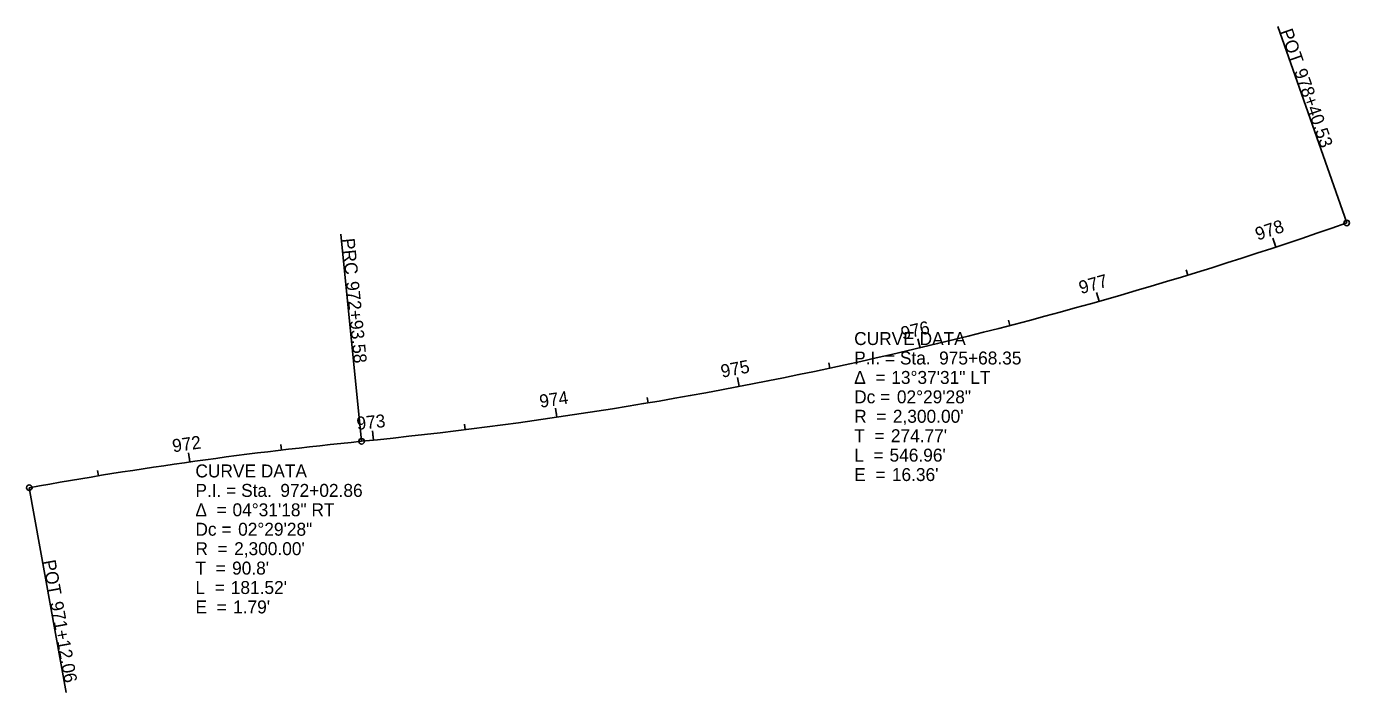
# Model space of a CAD drawing. Extents: x 2192763 to 2198189, y 660254 to 661868.
# Drawn here: x 2192763 to 2193478, y 660254 to 660614 of the extents above; entities that cross this region are included whole.
import ezdxf

# ---------------------------------------------------------------- set-up
doc = ezdxf.new("R2010")
doc.units = 0
for name, color, linetype in [('PM_X_Cells', 7, 'Continuous'), ('PM_X_CL_Double_Solid', 7, 'Continuous'), ('PM_X_Crosswalk', 7, 'Continuous'), ('PM_X_Dotted_Line', 7, 'Continuous'), ('PM_X_Edge_Line', 7, 'Continuous'), ('PM_X_Stop_Line', 7, 'Continuous'), ('PM_X_Yield_Line', 7, 'Continuous')]:
    doc.layers.add(name, color=color, linetype=linetype)

msp = doc.modelspace()

# ---------------------------------------------------------------- linework, layer by layer
at = {"layer": 'PM_X_Cells'}
for p, q in [((2193476.77, 660508.15), (2193439.57, 660614.32)), ((2192944.02, 660390.1), (2192932.88, 660502.04)), ((2193148.24, 660419.72), (2193147.68, 660422.66)), ((2192764.29, 660365.02), (2192784.22, 660254.3))]:
    msp.add_line(p, q, dxfattribs=at)
for centre in [(2193476.77, 660508.15), (2192944.02, 660390.1), (2192764.29, 660365.02)]:
    msp.add_circle(centre, 1.5, dxfattribs=at)
at = {"layer": 'PM_X_CL_Double_Solid'}
for p, q in [((2193476.77, 660508.15), (2193439.57, 660614.32)), ((2192944.02, 660390.1), (2192932.88, 660502.04)), ((2193438.4, 660495.08), (2193437.46, 660497.93)), ((2193342.8, 660465.76), (2193341.98, 660468.65)), ((2193246.02, 660440.62), (2193245.33, 660443.54)), ((2193148.24, 660419.72), (2193147.3, 660424.63)), ((2193049.64, 660403.08), (2193049.21, 660406.05)), ((2192950.41, 660390.74), (2192950.11, 660393.72)), ((2192851.12, 660378.94), (2192850.7, 660381.91)), ((2192764.29, 660365.02), (2192784.22, 660254.3))]:
    msp.add_line(p, q, dxfattribs=at)
for centre in [(2193476.77, 660508.15), (2192944.02, 660390.1), (2192764.29, 660365.02)]:
    msp.add_circle(centre, 1.5, dxfattribs=at)
at = {"layer": 'PM_X_Edge_Line'}
for centre, start, end in [((2192716.32, 662678.8), 275.68173, 289.30709), ((2193171.73, 658101.39), 95.68173, 100.20349)]:
    msp.add_arc(centre, 2300, start, end, dxfattribs=at)
at = {"layer": 'PM_X_Yield_Line'}
for p, q in [((2193476.77, 660508.15), (2193439.57, 660614.32)), ((2192944.02, 660390.1), (2192932.88, 660502.04)), ((2193438.4, 660495.08), (2193436.83, 660499.83)), ((2193390.76, 660479.9), (2193389.88, 660482.77)), ((2193342.8, 660465.76), (2193341.44, 660470.57)), ((2193294.55, 660452.67), (2193293.79, 660455.57)), ((2193246.02, 660440.62), (2193244.87, 660445.49)), ((2193197.24, 660429.64), (2193196.62, 660432.57)), ((2193148.24, 660419.72), (2193147.3, 660424.63)), ((2193099.03, 660410.86), (2193098.53, 660413.82)), ((2193049.64, 660403.08), (2193048.92, 660408.02)), ((2193000.09, 660396.37), (2192999.72, 660399.35)), ((2192950.41, 660390.74), (2192949.9, 660395.71)), ((2192851.12, 660378.94), (2192850.42, 660383.89)), ((2192900.7, 660385.37), (2192900.35, 660388.35)), ((2192801.69, 660371.43), (2192801.2, 660374.39)), ((2192764.29, 660365.02), (2192784.22, 660254.3))]:
    msp.add_line(p, q, dxfattribs=at)
for centre in [(2193476.77, 660508.15), (2192944.02, 660390.1), (2192764.29, 660365.02)]:
    msp.add_circle(centre, 1.5, dxfattribs=at)

# ---------------------------------------------------------------- texts
at = {"layer": 'PM_X_Cells'}
for s, rotation, p in [('POT', 289.30709, (2193440.62, 660611.68)), ('978+40.53', 289.30709, (2193448.17, 660590.14)), ('PRC', 275.68173, (2192933.25, 660499.53)), ('972+93.58', 275.68173, (2192935.56, 660476.28)), ('POT', 280.20349, (2192771.55, 660325.39)), ('971+12.06', 280.20349, (2192775.59, 660302.92))]:
    msp.add_text(s, height=7, rotation=rotation, dxfattribs=at).set_placement(p)
at = {"layer": 'PM_X_CL_Double_Solid'}
for s, rotation, p in [('POT', 289.30709, (2193440.62, 660611.68)), ('978+40.53', 289.30709, (2193448.17, 660590.14)), ('PRC', 275.68173, (2192933.25, 660499.53)), ('972+93.58', 275.68173, (2192935.56, 660476.28)), ('975', 10.82402, (2193138.95, 660424.42)), ('POT', 280.20349, (2192771.55, 660325.39)), ('971+12.06', 280.20349, (2192775.59, 660302.92))]:
    msp.add_text(s, height=7, rotation=rotation, dxfattribs=at).set_placement(p)
at = {"layer": 'PM_X_Crosswalk'}
for s, p in [('CURVE DATA', (2193210.39, 660442.12)), ('P.I. = Sta. ', (2193210.39, 660431.62)), ('975+68.35', (2193256.32, 660431.62)), ('Δ  = ', (2193210.39, 660421.12)), ('13°37\'31" LT', (2193230.45, 660421.12)), ('Dc = ', (2193210.39, 660410.62)), ('02°29\'28"', (2193233.49, 660410.62)), ('R  = ', (2193210.39, 660400.12)), ("2,300.00'", (2193231.31, 660400.12)), ('T  = ', (2193210.39, 660389.62)), ("274.77'", (2193230.23, 660389.62)), ('L  = ', (2193210.39, 660379.12)), ("546.96'", (2193229.51, 660379.12)), ('CURVE DATA', (2192854.16, 660370.56)), ('E  = ', (2193210.39, 660368.62)), ("16.36'", (2193230.77, 660368.62)), ('P.I. = Sta. ', (2192854.16, 660360.06)), ('972+02.86', (2192900.08, 660360.06)), ('Δ  = ', (2192854.16, 660349.56)), ('04°31\'18" RT', (2192874.21, 660349.56)), ('Dc = ', (2192854.16, 660339.06)), ('02°29\'28"', (2192877.25, 660339.06)), ('R  = ', (2192854.16, 660328.56)), ("2,300.00'", (2192875.08, 660328.56)), ('T  = ', (2192854.16, 660318.06)), ("90.8'", (2192873.99, 660318.06)), ('L  = ', (2192854.16, 660307.56)), ("181.52'", (2192873.27, 660307.56)), ('E  = ', (2192854.16, 660297.06)), ("1.79'", (2192874.54, 660297.06))]:
    msp.add_text(s, height=7, dxfattribs=at).set_placement(p)
at = {"layer": 'PM_X_Dotted_Line'}
for s, p in [('CURVE DATA', (2193210.39, 660442.12)), ('P.I. = Sta. ', (2193210.39, 660431.62)), ('975+68.35', (2193256.32, 660431.62)), ('Δ  = ', (2193210.39, 660421.12)), ('13°37\'31" LT', (2193230.45, 660421.12)), ('Dc = ', (2193210.39, 660410.62)), ('02°29\'28"', (2193233.49, 660410.62)), ('R  = ', (2193210.39, 660400.12)), ("2,300.00'", (2193231.31, 660400.12)), ('T  = ', (2193210.39, 660389.62)), ("274.77'", (2193230.23, 660389.62)), ('L  = ', (2193210.39, 660379.12)), ("546.96'", (2193229.51, 660379.12)), ('CURVE DATA', (2192854.16, 660370.56)), ('E  = ', (2193210.39, 660368.62)), ("16.36'", (2193230.77, 660368.62)), ('P.I. = Sta. ', (2192854.16, 660360.06)), ('972+02.86', (2192900.08, 660360.06)), ('Δ  = ', (2192854.16, 660349.56)), ('04°31\'18" RT', (2192874.21, 660349.56)), ('Dc = ', (2192854.16, 660339.06)), ('02°29\'28"', (2192877.25, 660339.06)), ('R  = ', (2192854.16, 660328.56)), ("2,300.00'", (2192875.08, 660328.56)), ('T  = ', (2192854.16, 660318.06)), ("90.8'", (2192873.99, 660318.06)), ('L  = ', (2192854.16, 660307.56)), ("181.52'", (2192873.27, 660307.56)), ('E  = ', (2192854.16, 660297.06)), ("1.79'", (2192874.54, 660297.06))]:
    msp.add_text(s, height=7, dxfattribs=at).set_placement(p)
at = {"layer": 'PM_X_Stop_Line'}
for s, p in [('CURVE DATA', (2193210.39, 660442.12)), ('P.I. = Sta. ', (2193210.39, 660431.62)), ('975+68.35', (2193256.32, 660431.62)), ('Δ  = ', (2193210.39, 660421.12)), ('13°37\'31" LT', (2193230.45, 660421.12)), ('Dc = ', (2193210.39, 660410.62)), ('02°29\'28"', (2193233.49, 660410.62)), ('R  = ', (2193210.39, 660400.12)), ("2,300.00'", (2193231.31, 660400.12)), ('T  = ', (2193210.39, 660389.62)), ("274.77'", (2193230.23, 660389.62)), ('L  = ', (2193210.39, 660379.12)), ("546.96'", (2193229.51, 660379.12)), ('CURVE DATA', (2192854.16, 660370.56)), ('E  = ', (2193210.39, 660368.62)), ("16.36'", (2193230.77, 660368.62)), ('P.I. = Sta. ', (2192854.16, 660360.06)), ('972+02.86', (2192900.08, 660360.06)), ('Δ  = ', (2192854.16, 660349.56)), ('04°31\'18" RT', (2192874.21, 660349.56)), ('Dc = ', (2192854.16, 660339.06)), ('02°29\'28"', (2192877.25, 660339.06)), ('R  = ', (2192854.16, 660328.56)), ("2,300.00'", (2192875.08, 660328.56)), ('T  = ', (2192854.16, 660318.06)), ("90.8'", (2192873.99, 660318.06)), ('L  = ', (2192854.16, 660307.56)), ("181.52'", (2192873.27, 660307.56)), ('E  = ', (2192854.16, 660297.06)), ("1.79'", (2192874.54, 660297.06))]:
    msp.add_text(s, height=7, dxfattribs=at).set_placement(p)
at = {"layer": 'PM_X_Yield_Line'}
for s, rotation, p in [('POT', 289.30709, (2193440.62, 660611.68)), ('978+40.53', 289.30709, (2193448.17, 660590.14)), ('978', 18.29738, (2193428.62, 660498.56)), ('PRC', 275.68173, (2192933.25, 660499.53)), ('972+93.58', 275.68173, (2192935.56, 660476.28)), ('977', 15.80626, (2193333.04, 660469.62)), ('976', 13.31514, (2193236.56, 660444.93)), ('975', 10.82402, (2193138.95, 660424.42)), ('974', 8.3329, (2193040.71, 660408.2)), ('973', 5.84178, (2192941.65, 660396.24)), ('972', 8.0128, (2192842.13, 660384.1)), ('POT', 280.20349, (2192771.55, 660325.39)), ('971+12.06', 280.20349, (2192775.59, 660302.92))]:
    msp.add_text(s, height=7, rotation=rotation, dxfattribs=at).set_placement(p)

doc.saveas('drawing.dxf')
